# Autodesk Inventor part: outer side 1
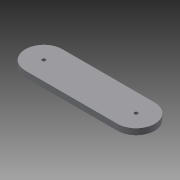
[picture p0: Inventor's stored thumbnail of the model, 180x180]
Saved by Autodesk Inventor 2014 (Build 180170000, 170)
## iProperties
Created: 2015-01
Part Number: outer side 1
Material: Generic
Document SubType Name: Modeling
Designer: Drano
Density: 1 g/cm^3
Appearance: Default
Author: Drano
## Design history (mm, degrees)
sketch "Sketch1" dims "d0" = 5
  geometry: L1 (-39.389, -16.629)-(37.611, -16.629); L2 (-39.389, 14.371)-(37.611, 14.371); C1 r 1.5 at (-39.389, -1.129); C2 r 1.5 at (37.611, -1.129); A1 r 15.5 centre (37.611, -1.129) between (37.611, -16.629) and (37.611, 14.371); A2 r 15.5 centre (-39.389, -1.129) between (-39.389, 14.371) and (-39.389, -16.629); 1 further point
  constraints: 4 centre point, 4 end point, 4 point on circle
extrude "Extrusion1" new body sketch "Sketch1" distance "d0" = 5; taper "d1" = 0 deg
body "Solid1"
